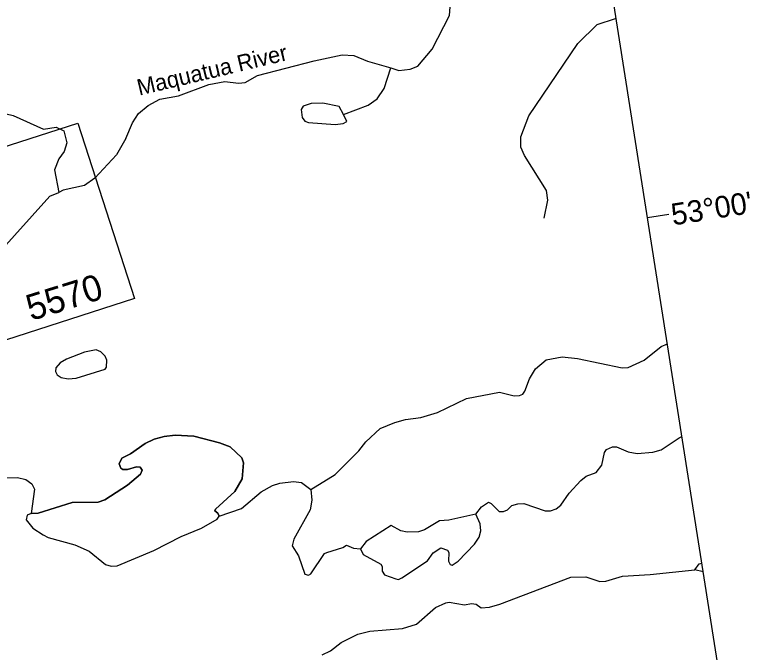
# Model space of a CAD drawing. Extents: x 643342 to 646936, y 5873857 to 5876103.
# Drawn here: x 646548.6 to 646684.5, y 5875301 to 5875418.5 of the extents above; entities that cross this region are included whole.
import ezdxf

# ---------------------------------------------------------------- set-up
doc = ezdxf.new("R2010")
doc.units = 0
doc.layers.add('Niveau 63', color=7, linetype='Continuous')

msp = doc.modelspace()

# ---------------------------------------------------------------- linework, layer by layer
at = {"layer": 'Niveau 63'}
for p, q in [((646608.37, 5875401.57), (646605.34, 5875402.15)), ((646601.35, 5875401.03), (646601.5, 5875399.54)), ((646609.15, 5875400.07), (646608.37, 5875401.57)), ((646601.5, 5875399.54), (646602.01, 5875398.87)), ((646609.78, 5875398.8), (646609.15, 5875400.07)), ((646602.01, 5875398.87), (646602.7, 5875398.61)), ((646602.7, 5875398.61), (646607.59, 5875398.25)), ((646607.59, 5875398.25), (646609.09, 5875398.4)), ((646609.09, 5875398.4), (646609.78, 5875398.8)), ((646665.17, 5875381.09), (646669.12, 5875381.71)), ((646565.56, 5875354.79), (646565.24, 5875355.55)), ((646565.46, 5875353.48), (646565.56, 5875354.79)), ((646558.42, 5875351.36), (646559.87, 5875351.46)), ((646576.09, 5875340.75), (646574.24, 5875340.26)), ((646578.14, 5875340.98), (646576.09, 5875340.75)), ((646581.57, 5875340.81), (646578.14, 5875340.98)), ((646574.24, 5875340.26), (646572.61, 5875339.46)), ((646568.28, 5875336.73), (646567.82, 5875335.67)), ((646571.65, 5875335.1), (646572.07, 5875334.51)), ((646590.46, 5875332.93), (646590.72, 5875335.89)), ((646571.71, 5875333.81), (646569.36, 5875331.76)), ((646572.07, 5875334.51), (646571.71, 5875333.81)), ((646589.12, 5875330.6), (646590.46, 5875332.93)), ((646569.36, 5875331.76), (646565.18, 5875329.04)), ((646585.53, 5875327.34), (646589.12, 5875330.6)), ((646585.44, 5875327), (646585.53, 5875327.34)), ((646585.98, 5875326.62), (646585.44, 5875327)), ((646585.88, 5875325.47), (646586.26, 5875326.02)), ((646586.26, 5875326.02), (646585.98, 5875326.62)), ((646634.34, 5875324.63), (646633.54, 5875326.41)), ((646626.81, 5875325.17), (646624.05, 5875323.52)), ((646634.42, 5875323.35), (646634.34, 5875324.63)), ((646624.05, 5875323.52), (646622.99, 5875323.17)), ((646634.16, 5875322.17), (646634.42, 5875323.35)), ((646553.78, 5875322.57), (646554.69, 5875322.08)), ((646554.69, 5875322.08), (646559.62, 5875320.73)), ((646633.27, 5875320.88), (646634.16, 5875322.17)), ((646559.62, 5875320.73), (646562.25, 5875319.61)), ((646630.3, 5875317.74), (646633.27, 5875320.88)), ((646562.25, 5875319.61), (646565.31, 5875317.11)), ((646567.46, 5875316.86), (646574.19, 5875319.72)), ((646612.27, 5875320.05), (646612.78, 5875318.99)), ((646628.55, 5875319.35), (646628.52, 5875317.72)), ((646565.31, 5875317.11), (646566.33, 5875316.81)), ((646566.33, 5875316.81), (646567.46, 5875316.86)), ((646616.27, 5875316.75), (646616.25, 5875315.93)), ((646616.25, 5875315.93), (646616.71, 5875315.22)), ((646616.71, 5875315.22), (646618.79, 5875314.47)), ((646618.79, 5875314.47), (646619.29, 5875314.39))]:
    msp.add_line(p, q, dxfattribs=at)
msp.add_lwpolyline([(646368.36, 5875208.69), (646684.47, 5875258.43), (646647.17, 5875495.51), (646331.05, 5875445.78)], close=True, dxfattribs=at)
for points in [[(646617.84, 5875408.69), (646619.33, 5875408.19), (646621.45, 5875408.47), (646622.87, 5875408.97), (646625.47, 5875412.14), (646628.65, 5875418.33), (646628.93, 5875421.55), (646630.1, 5875423.55), (646632.3, 5875425.99), (646634.47, 5875427.42), (646638.54, 5875428.69), (646640.33, 5875430.02), (646641.85, 5875432.08)], [(646646.1, 5875381), (646646.8, 5875384.31), (646646.58, 5875386.06), (646642.47, 5875392.54), (646641.8, 5875394.07), (646641.82, 5875395.98), (646643.27, 5875399.81), (646652.33, 5875413.2), (646655.88, 5875416.66), (646659.24, 5875417.79), (646659.38, 5875417.9)], [(646569.05, 5875395.65), (646570.29, 5875398.56), (646571.36, 5875400.28), (646573.13, 5875401.76), (646575.31, 5875402.93), (646578.76, 5875403.55), (646584.35, 5875405.63), (646587.3, 5875406.17), (646589.77, 5875405.87), (646591.03, 5875405.97), (646593.31, 5875407.3), (646603.74, 5875409.99), (646608.88, 5875411.08), (646611.06, 5875410.98), (646613.55, 5875409.92), (646617.84, 5875408.69)], [(646609.15, 5875400.07), (646613.66, 5875401.79), (646615.35, 5875402.99), (646616.65, 5875404.9), (646617.84, 5875408.69)], [(646605.34, 5875402.15), (646603.18, 5875402.13), (646601.74, 5875401.62), (646601.35, 5875401.03)], [(646609.78, 5875398.8), (646609.15, 5875400.07), (646608.37, 5875401.57), (646605.34, 5875402.15), (646603.18, 5875402.13), (646601.74, 5875401.62), (646601.35, 5875401.03), (646601.5, 5875399.54), (646602.01, 5875398.87), (646602.7, 5875398.61), (646607.59, 5875398.25), (646609.09, 5875398.4), (646609.78, 5875398.8)], [(646537.17, 5875394.8), (646542.83, 5875398.65), (646544.89, 5875399.8), (646546.98, 5875400.19), (646548.3, 5875399.91), (646553.85, 5875397.41), (646556.21, 5875397.72), (646557.61, 5875397.09), (646558.14, 5875394.88), (646557.68, 5875393.27), (646556.66, 5875391.94), (646555.89, 5875389.89), (646556.66, 5875385.72)], [(646537.17, 5875394.8), (646542.83, 5875398.65), (646544.89, 5875399.8), (646546.98, 5875400.19), (646548.3, 5875399.91), (646553.85, 5875397.41), (646556.21, 5875397.72), (646557.61, 5875397.09), (646558.14, 5875394.88), (646557.68, 5875393.27), (646556.66, 5875391.94), (646555.89, 5875389.89), (646556.66, 5875385.72)], [(646519.23, 5875349.58), (646508.79, 5875381.93), (646560.18, 5875398.51), (646570.62, 5875366.16), (646519.23, 5875349.58)], [(646569.05, 5875395.65), (646567.31, 5875392.66), (646563.3, 5875388.34), (646561.39, 5875386.97), (646557.49, 5875386.11), (646556.66, 5875385.72)], [(646532.82, 5875359.58), (646534.01, 5875366.12), (646534.9, 5875367.42), (646541.1, 5875372.4), (646543.27, 5875373.69), (646545.22, 5875374.18), (646555.01, 5875385.04), (646556.66, 5875385.72)], [(646603.12, 5875330.94), (646607.61, 5875333.71), (646611.96, 5875338.08), (646613.27, 5875339.76), (646615.89, 5875342.2), (646618.58, 5875343.33), (646620.58, 5875343.87), (646623.42, 5875344.23), (646626.48, 5875345.14), (646631.82, 5875347.74), (646637.9, 5875348.88), (646640.61, 5875348.25), (646641.58, 5875348.26), (646642.16, 5875348.54), (646642.54, 5875349.08), (646643.42, 5875351.35), (646644.53, 5875353.18), (646646.5, 5875354.83), (646649.44, 5875355.39), (646652.26, 5875355.11), (646660.49, 5875353.4), (646661.62, 5875353.44), (646664.58, 5875354.8), (646667.66, 5875357.33), (646668.83, 5875357.81)], [(646565.24, 5875355.55), (646564.44, 5875356.35), (646563.58, 5875356.68), (646561.4, 5875356.28), (646558.07, 5875355.01), (646556.91, 5875354.32), (646556.13, 5875353.36), (646556.09, 5875352.71)], [(646561.4, 5875356.28), (646558.07, 5875355.01), (646556.91, 5875354.32), (646556.13, 5875353.36), (646556.09, 5875352.71), (646556.36, 5875352.11), (646557.09, 5875351.59), (646558.42, 5875351.36), (646559.87, 5875351.46), (646565.21, 5875353.11), (646565.46, 5875353.48), (646565.56, 5875354.79), (646565.24, 5875355.55), (646564.44, 5875356.35), (646563.58, 5875356.68), (646561.4, 5875356.28)], [(646563.58, 5875356.68), (646561.4, 5875356.28), (646558.07, 5875355.01), (646556.91, 5875354.32), (646556.13, 5875353.36), (646556.09, 5875352.71), (646556.36, 5875352.11), (646557.09, 5875351.59), (646558.42, 5875351.36), (646559.87, 5875351.46), (646565.21, 5875353.11), (646565.46, 5875353.48), (646565.56, 5875354.79), (646565.24, 5875355.55), (646564.44, 5875356.35), (646563.58, 5875356.68)], [(646561.4, 5875356.28), (646558.07, 5875355.01), (646556.91, 5875354.32), (646556.13, 5875353.36), (646556.09, 5875352.71), (646556.36, 5875352.11), (646557.09, 5875351.59), (646558.42, 5875351.36), (646559.87, 5875351.46), (646565.21, 5875353.11), (646565.46, 5875353.48), (646565.56, 5875354.79), (646565.24, 5875355.55), (646564.44, 5875356.35), (646563.58, 5875356.68), (646561.4, 5875356.28)], [(646563.58, 5875356.68), (646561.4, 5875356.28), (646558.07, 5875355.01), (646556.91, 5875354.32), (646556.13, 5875353.36), (646556.09, 5875352.71), (646556.36, 5875352.11), (646557.09, 5875351.59), (646558.42, 5875351.36), (646559.87, 5875351.46), (646565.21, 5875353.11), (646565.46, 5875353.48), (646565.56, 5875354.79), (646565.24, 5875355.55), (646564.44, 5875356.35), (646563.58, 5875356.68)], [(646559.87, 5875351.46), (646565.21, 5875353.11), (646565.46, 5875353.48)], [(646556.09, 5875352.71), (646556.36, 5875352.11), (646557.09, 5875351.59), (646558.42, 5875351.36)], [(646585.88, 5875325.47), (646586.26, 5875326.02), (646585.98, 5875326.62), (646585.44, 5875327), (646585.53, 5875327.34), (646589.12, 5875330.6), (646590.46, 5875332.93), (646590.72, 5875335.89), (646590.39, 5875336.81), (646588.24, 5875338.82), (646586.31, 5875339.59), (646581.57, 5875340.81), (646578.14, 5875340.98), (646576.09, 5875340.75), (646574.24, 5875340.26), (646572.61, 5875339.46), (646569.9, 5875337.51), (646568.28, 5875336.73), (646567.82, 5875335.67), (646568.12, 5875334.92), (646568.5, 5875334.66), (646569.31, 5875334.65), (646571, 5875335.13), (646571.65, 5875335.1), (646572.07, 5875334.51), (646571.71, 5875333.81), (646569.36, 5875331.76), (646565.18, 5875329.04), (646563.96, 5875328.64), (646559.14, 5875328.55), (646552.87, 5875326.59), (646551.6, 5875326.52), (646550.84, 5875326.21), (646550.67, 5875325.38), (646551.92, 5875323.83), (646553.78, 5875322.57), (646554.69, 5875322.08), (646559.62, 5875320.73), (646562.25, 5875319.61), (646565.31, 5875317.11), (646566.33, 5875316.81), (646567.46, 5875316.86), (646574.19, 5875319.72), (646579.2, 5875322.27), (646582.97, 5875323.8), (646585.88, 5875325.47)], [(646551.6, 5875326.52), (646552.87, 5875326.59), (646559.14, 5875328.55), (646563.96, 5875328.64), (646565.18, 5875329.04), (646569.36, 5875331.76), (646571.71, 5875333.81), (646572.07, 5875334.51), (646571.65, 5875335.1), (646571, 5875335.13), (646569.31, 5875334.65), (646568.5, 5875334.66), (646568.12, 5875334.92), (646567.82, 5875335.67), (646568.28, 5875336.73), (646569.9, 5875337.51), (646572.61, 5875339.46), (646574.24, 5875340.26), (646576.09, 5875340.75), (646578.14, 5875340.98), (646581.57, 5875340.81), (646586.31, 5875339.59), (646588.24, 5875338.82), (646590.39, 5875336.81), (646590.72, 5875335.89), (646590.46, 5875332.93), (646589.12, 5875330.6), (646585.53, 5875327.34), (646585.44, 5875327), (646585.98, 5875326.62), (646586.26, 5875326.02)], [(646551.6, 5875326.52), (646552.87, 5875326.59), (646559.14, 5875328.55), (646563.96, 5875328.64), (646565.18, 5875329.04), (646569.36, 5875331.76), (646571.71, 5875333.81), (646572.07, 5875334.51), (646571.65, 5875335.1), (646571, 5875335.13), (646569.31, 5875334.65), (646568.5, 5875334.66), (646568.12, 5875334.92), (646567.82, 5875335.67), (646568.28, 5875336.73), (646569.9, 5875337.51), (646572.61, 5875339.46), (646574.24, 5875340.26), (646576.09, 5875340.75), (646578.14, 5875340.98), (646581.57, 5875340.81), (646586.31, 5875339.59), (646588.24, 5875338.82), (646590.39, 5875336.81), (646590.72, 5875335.89), (646590.46, 5875332.93), (646589.12, 5875330.6), (646585.53, 5875327.34), (646585.44, 5875327), (646585.98, 5875326.62), (646586.26, 5875326.02)], [(646588.24, 5875338.82), (646586.31, 5875339.59), (646581.57, 5875340.81)], [(646633.54, 5875326.41), (646634.58, 5875327.75), (646635.86, 5875328.64), (646636.38, 5875328.39), (646637.81, 5875326.9), (646638.6, 5875326.88), (646639.37, 5875327.18), (646640.19, 5875327.98), (646641.25, 5875328.33), (646642.38, 5875328.39), (646646.33, 5875327.02), (646647.3, 5875327.04), (646648.36, 5875327.4), (646649.21, 5875328.04), (646650.74, 5875330.27), (646652.89, 5875332.61), (646653.87, 5875333.43), (646655.69, 5875334.08), (646656.74, 5875335.42), (646657.26, 5875337.77), (646657.63, 5875338.34), (646658.69, 5875338.85), (646659.48, 5875338.83), (646661.59, 5875337.93), (646663.28, 5875337.61), (646666.14, 5875337.81), (646667.67, 5875338.26), (646670.98, 5875340.5), (646671.52, 5875340.72)], [(646572.61, 5875339.46), (646569.9, 5875337.51), (646568.28, 5875336.73)], [(646590.72, 5875335.89), (646590.39, 5875336.81), (646588.24, 5875338.82)], [(646567.82, 5875335.67), (646568.12, 5875334.92), (646568.5, 5875334.66), (646569.31, 5875334.65)], [(646569.31, 5875334.65), (646571, 5875335.13), (646571.65, 5875335.1)], [(646544.56, 5875329.56), (646544.74, 5875330.4), (646545.69, 5875332.19), (646546.38, 5875332.8), (646547.13, 5875333.1), (646549.06, 5875333.14), (646550.59, 5875332.8), (646551.69, 5875332.02), (646552.22, 5875330.99), (646551.6, 5875326.52)], [(646544.56, 5875329.56), (646544.74, 5875330.4), (646545.69, 5875332.19), (646546.38, 5875332.8), (646547.13, 5875333.1), (646549.06, 5875333.14), (646550.59, 5875332.8), (646551.69, 5875332.02), (646552.22, 5875330.99), (646551.6, 5875326.52)], [(646586.26, 5875326.02), (646590.37, 5875327.43), (646593.99, 5875330.53), (646596.04, 5875331.7), (646597.41, 5875332.12), (646599.93, 5875332.44), (646601.42, 5875332.23), (646603.12, 5875330.94)], [(646603.12, 5875330.94), (646603.32, 5875329.02), (646603, 5875327.19), (646599.98, 5875321.8), (646599.71, 5875320.6), (646600.87, 5875318.72), (646601.99, 5875315.37), (646602.67, 5875315.17), (646603.11, 5875315.43), (646605.65, 5875319.13), (646606.07, 5875319.37), (646609, 5875320.24), (646609.71, 5875320.7), (646610.96, 5875320.12), (646612.27, 5875320.05)], [(646565.18, 5875329.04), (646563.96, 5875328.64), (646559.14, 5875328.55), (646552.87, 5875326.59), (646551.6, 5875326.52)], [(646551.6, 5875326.52), (646550.84, 5875326.21), (646550.67, 5875325.38)], [(646612.27, 5875320.05), (646612.78, 5875318.99), (646616.02, 5875317.17), (646616.27, 5875316.75), (646616.25, 5875315.93), (646616.71, 5875315.22), (646618.79, 5875314.47), (646619.29, 5875314.39), (646619.89, 5875314.67), (646624.62, 5875317.82), (646625.64, 5875319.3), (646627.1, 5875320.21), (646628.3, 5875319.79), (646628.55, 5875319.35), (646628.52, 5875317.72), (646628.8, 5875317.14), (646629.14, 5875317.03), (646630.3, 5875317.74), (646633.27, 5875320.88), (646634.16, 5875322.17), (646634.42, 5875323.35), (646634.34, 5875324.63), (646633.54, 5875326.41)], [(646612.27, 5875320.05), (646612.78, 5875318.99), (646616.02, 5875317.17), (646616.27, 5875316.75), (646616.25, 5875315.93), (646616.71, 5875315.22), (646618.79, 5875314.47), (646619.29, 5875314.39), (646619.89, 5875314.67), (646624.62, 5875317.82), (646625.64, 5875319.3), (646627.1, 5875320.21), (646628.3, 5875319.79), (646628.55, 5875319.35), (646628.52, 5875317.72), (646628.8, 5875317.14), (646629.14, 5875317.03), (646630.3, 5875317.74), (646633.27, 5875320.88), (646634.16, 5875322.17), (646634.42, 5875323.35), (646634.34, 5875324.63), (646633.54, 5875326.41)], [(646633.54, 5875326.41), (646628.56, 5875325.32), (646626.81, 5875325.17), (646624.05, 5875323.52), (646622.99, 5875323.17), (646620.9, 5875323.1), (646619.72, 5875323.36), (646617.93, 5875324.32), (646613.31, 5875321.36), (646612.27, 5875320.05), (646612.78, 5875318.99), (646616.02, 5875317.17), (646616.27, 5875316.75), (646616.25, 5875315.93), (646616.71, 5875315.22), (646618.79, 5875314.47), (646619.29, 5875314.39), (646619.89, 5875314.67), (646624.62, 5875317.82), (646625.64, 5875319.3), (646627.1, 5875320.21), (646628.3, 5875319.79), (646628.55, 5875319.35), (646628.52, 5875317.72), (646628.8, 5875317.14), (646629.14, 5875317.03), (646630.3, 5875317.74), (646633.27, 5875320.88), (646634.16, 5875322.17), (646634.42, 5875323.35), (646634.34, 5875324.63), (646633.54, 5875326.41)], [(646633.54, 5875326.41), (646628.56, 5875325.32), (646626.81, 5875325.17)], [(646550.67, 5875325.38), (646551.92, 5875323.83), (646553.78, 5875322.57)], [(646574.19, 5875319.72), (646579.2, 5875322.27), (646582.97, 5875323.8), (646585.88, 5875325.47)], [(646617.93, 5875324.32), (646613.31, 5875321.36), (646612.27, 5875320.05)], [(646622.99, 5875323.17), (646620.9, 5875323.1), (646619.72, 5875323.36), (646617.93, 5875324.32)], [(646624.62, 5875317.82), (646625.64, 5875319.3), (646627.1, 5875320.21)], [(646627.1, 5875320.21), (646628.3, 5875319.79), (646628.55, 5875319.35)], [(646612.78, 5875318.99), (646616.02, 5875317.17), (646616.27, 5875316.75)], [(646619.29, 5875314.39), (646619.89, 5875314.67), (646624.62, 5875317.82)], [(646628.52, 5875317.72), (646628.8, 5875317.14), (646629.14, 5875317.03), (646630.3, 5875317.74)], [(646605.24, 5875300.48), (646606.72, 5875301.23), (646608.69, 5875302.74), (646611.81, 5875304.28), (646613.97, 5875304.85), (646620.01, 5875305.33), (646622.62, 5875306.12), (646626.08, 5875309.2), (646628.01, 5875310.05), (646628.64, 5875310.17), (646631.46, 5875309.72), (646632.72, 5875309.96), (646633.56, 5875309.79), (646634.49, 5875309.15), (646636.07, 5875309.27), (646637.93, 5875309.79), (646651.05, 5875314.81), (646653.78, 5875314.83), (646656.36, 5875314.02), (646657.48, 5875314.08), (646660.54, 5875314.97), (646665.66, 5875315.27), (646673.9, 5875316.16)], [(646673.9, 5875316.16), (646674.66, 5875317.27), (646675.19, 5875317.37)], [(646675.44, 5875315.8), (646673.9, 5875316.16)]]:
    msp.add_lwpolyline(points, dxfattribs=at)

# ---------------------------------------------------------------- texts
for s, height, rotation, p in [('Maquatua River', 3, 13.4862, (646571.5, 5875403.55)), ("53°00'", 4, 8.9411, (646669.86, 5875379.63)), ("53°00'", 4, 8.9411, (646669.86, 5875379.63)), ('5570', 4.8, 17.2718, (646551.56, 5875362.01))]:
    msp.add_text(s, height=height, rotation=rotation, dxfattribs=at).set_placement(p)

doc.saveas('drawing.dxf')
